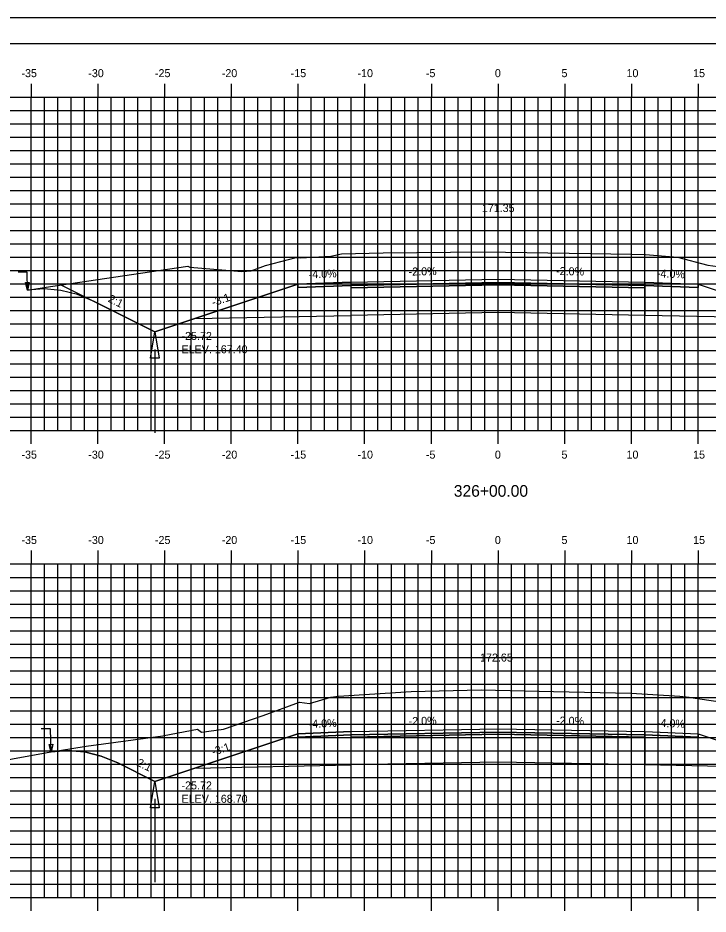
# Model space of a CAD drawing. Extents: x 1140537 to 1140707, y 608981 to 609091.
# Drawn here: x 1140584.3 to 1140636, y 609024.1 to 609091.3 of the extents above; entities that cross this region are included whole.
import ezdxf

# ---------------------------------------------------------------- set-up
doc = ezdxf.new("R2010")
doc.units = 0
for name, color, linetype in [('ANNOTATION', 7, 'Continuous'), ('BORDER', 7, 'Continuous'), ('D_Drainage_Ditch_Line', 7, 'Continuous'), ('D_Roadway_Centerline', 7, 'Continuous'), ('D_Roadway_Centerline_Text', 7, 'Continuous'), ('D_Roadway_Edge_Shoulder', 7, 'Continuous'), ('D_Roadway_Edge_TW', 7, 'Continuous'), ('D_Roadway_Pavement', 7, 'Continuous'), ('D_Roadway_SlopeLines', 7, 'Continuous'), ('D_Roadway_SubGrade', 7, 'Continuous'), ('D_Text_Standard', 7, 'Continuous'), ('H_V ANNOTATION', 7, 'Continuous'), ('MAJOR', 7, 'Continuous'), ('MINOR', 7, 'Continuous'), ('PLOT BOUNDARY', 7, 'Continuous'), ('S_Roadway_Centerline', 7, 'Continuous')]:
    doc.layers.add(name, color=color, linetype=linetype)

msp = doc.modelspace()

# ---------------------------------------------------------------- linework, layer by layer
for points in [[(1140587.473, 609071.258), (1140594.52, 609067.734), (1140597.52, 609068.734), (1140605.244, 609071.309), (1140605.245, 609071.309), (1140609.245, 609071.469), (1140620.245, 609071.689), (1140631.245, 609071.469), (1140635.245, 609071.309), (1140642.968, 609068.735), (1140645.968, 609067.735), (1140660.465, 609074.983), (1140661.715, 609075.533), (1140662.965, 609075.935), (1140664.215, 609076.188), (1140665.465, 609076.292)], [(1140586.756, 609036.254), (1140588.006, 609036.356), (1140589.256, 609036.25), (1140590.506, 609035.937), (1140591.756, 609035.416), (1140594.52, 609034.034), (1140597.52, 609035.034), (1140605.244, 609037.608), (1140605.245, 609037.608), (1140609.245, 609037.768), (1140620.245, 609037.988), (1140631.245, 609037.768), (1140635.245, 609037.608), (1140642.968, 609035.034), (1140645.968, 609034.034), (1140656.415, 609039.257), (1140657.665, 609039.806), (1140658.915, 609040.202), (1140660.165, 609040.445), (1140661.415, 609040.536)]]:
    msp.add_lwpolyline(points)
at = {"layer": 'BORDER'}
msp.add_lwpolyline([(1140545.245, 608984.335), (1140705.245, 608984.335), (1140705.245, 609089.335), (1140545.245, 609089.335)], close=True, dxfattribs=at)
at = {"layer": 'D_Drainage_Ditch_Line'}
for p, q in [((1140594.52, 609066.422), (1140594.52, 609060.179)), ((1140594.52, 609032.721), (1140594.52, 609026.478))]:
    msp.add_line(p, q, dxfattribs=at)
for points in [[(1140594.848, 609065.766), (1140594.192, 609065.766), (1140594.52, 609067.734)], [(1140594.848, 609032.065), (1140594.192, 609032.065), (1140594.52, 609034.034)]]:
    msp.add_lwpolyline(points, close=True, dxfattribs=at)
at = {"layer": 'D_Roadway_Edge_Shoulder'}
for points in [[(1140609.245, 609071.469), (1140605.245, 609071.309), (1140605.245, 609071.059), (1140609.245, 609071.219)], [(1140631.245, 609071.469), (1140635.245, 609071.309), (1140635.245, 609071.059), (1140631.245, 609071.219)], [(1140609.245, 609037.768), (1140605.245, 609037.608), (1140605.245, 609037.358), (1140609.245, 609037.518)], [(1140631.245, 609037.768), (1140635.245, 609037.608), (1140635.245, 609037.358), (1140631.245, 609037.518)]]:
    msp.add_lwpolyline(points, close=True, dxfattribs=at)
at = {"layer": 'D_Roadway_Edge_TW'}
for points in [[(1140609.245, 609071.219), (1140609.245, 609071.469), (1140620.245, 609071.689), (1140631.245, 609071.469), (1140631.245, 609071.219), (1140620.245, 609071.439)], [(1140609.245, 609037.518), (1140609.245, 609037.768), (1140620.245, 609037.988), (1140631.245, 609037.768), (1140631.245, 609037.518), (1140620.245, 609037.738)]]:
    msp.add_lwpolyline(points, close=True, dxfattribs=at)
at = {"layer": 'D_Roadway_Pavement'}
for points in [[(1140609.245, 609071.052), (1140609.245, 609071.219), (1140620.245, 609071.439), (1140631.245, 609071.219), (1140631.245, 609071.052), (1140620.245, 609071.272)], [(1140609.245, 609037.351), (1140609.245, 609037.518), (1140620.245, 609037.738), (1140631.245, 609037.518), (1140631.245, 609037.351), (1140620.245, 609037.571)]]:
    msp.add_lwpolyline(points, close=True, dxfattribs=at)
at = {"layer": 'D_Roadway_SlopeLines'}
for points in [[(1140594.52, 609067.734), (1140589.968, 609070.016), (1140588.718, 609070.537), (1140587.468, 609070.85), (1140586.218, 609070.956), (1140584.968, 609070.854)], [(1140597.52, 609068.734), (1140594.52, 609067.734)], [(1140594.52, 609034.034), (1140591.756, 609035.416), (1140590.506, 609035.937), (1140589.256, 609036.25), (1140588.006, 609036.356), (1140586.756, 609036.254)], [(1140597.52, 609035.034), (1140594.52, 609034.034)]]:
    msp.add_lwpolyline(points, dxfattribs=at)
at = {"layer": 'D_Roadway_SubGrade'}
for points in [[(1140609.245, 609071.052), (1140609.245, 609071.219), (1140605.245, 609071.059), (1140605.245, 609071.309), (1140605.244, 609071.309), (1140597.52, 609068.734), (1140609.245, 609068.969)], [(1140609.245, 609068.969), (1140609.245, 609071.052), (1140620.245, 609071.272), (1140631.245, 609071.052), (1140631.245, 609068.969), (1140620.245, 609069.189)], [(1140631.245, 609071.052), (1140631.245, 609071.219), (1140635.245, 609071.059), (1140635.245, 609071.309), (1140635.245, 609071.309), (1140642.968, 609068.735), (1140631.245, 609068.969)], [(1140609.245, 609037.351), (1140609.245, 609037.518), (1140605.245, 609037.358), (1140605.245, 609037.608), (1140605.244, 609037.608), (1140597.52, 609035.034), (1140609.245, 609035.268)], [(1140609.245, 609035.268), (1140609.245, 609037.351), (1140620.245, 609037.571), (1140631.245, 609037.351), (1140631.245, 609035.268), (1140620.245, 609035.488)], [(1140631.245, 609037.351), (1140631.245, 609037.518), (1140635.245, 609037.358), (1140635.245, 609037.608), (1140635.245, 609037.608), (1140642.968, 609035.034), (1140631.245, 609035.268)]]:
    msp.add_lwpolyline(points, close=True, dxfattribs=at)
at = {"layer": 'D_Text_Standard'}
for points in [[(1140584.968, 609070.854), (1140584.956, 609072.215), (1140584.276, 609072.215)], [(1140586.756, 609036.227), (1140586.691, 609037.975), (1140586.011, 609037.975)]]:
    msp.add_lwpolyline(points, dxfattribs=at)
for points in [[(1140584.968, 609070.854), (1140584.817, 609071.435), (1140585.108, 609071.438)], [(1140586.756, 609036.227), (1140586.589, 609036.804), (1140586.88, 609036.815)]]:
    msp.add_lwpolyline(points, close=True, dxfattribs=at)
at = {"layer": 'MAJOR'}
for p, q in [((1140585.245, 609086.337), (1140585.245, 609085.335)), ((1140590.245, 609086.337), (1140590.245, 609085.335)), ((1140595.245, 609086.337), (1140595.245, 609085.335)), ((1140600.245, 609086.337), (1140600.245, 609085.335)), ((1140605.245, 609086.337), (1140605.245, 609085.335)), ((1140610.245, 609086.337), (1140610.245, 609085.335)), ((1140615.245, 609086.337), (1140615.245, 609085.335)), ((1140620.245, 609086.337), (1140620.245, 609085.335)), ((1140625.245, 609086.337), (1140625.245, 609085.335)), ((1140630.245, 609086.337), (1140630.245, 609085.335)), ((1140635.245, 609086.337), (1140635.245, 609085.335)), ((1140550.245, 609085.335), (1140690.245, 609085.335)), ((1140550.245, 609085.335), (1140690.245, 609085.335)), ((1140585.245, 609060.335), (1140585.245, 609085.335)), ((1140590.245, 609060.335), (1140590.245, 609085.335)), ((1140595.245, 609060.335), (1140595.245, 609085.335)), ((1140600.245, 609060.335), (1140600.245, 609085.335)), ((1140605.245, 609060.335), (1140605.245, 609085.335)), ((1140610.245, 609060.335), (1140610.245, 609085.335)), ((1140615.245, 609060.335), (1140615.245, 609085.335)), ((1140620.245, 609060.335), (1140620.245, 609085.335)), ((1140625.245, 609060.335), (1140625.245, 609085.335)), ((1140630.245, 609060.335), (1140630.245, 609085.335)), ((1140635.245, 609060.335), (1140635.245, 609085.335)), ((1140550.245, 609080.335), (1140690.245, 609080.335)), ((1140550.245, 609075.335), (1140690.245, 609075.335)), ((1140550.245, 609070.335), (1140690.245, 609070.335)), ((1140550.245, 609065.335), (1140690.245, 609065.335)), ((1140550.245, 609060.335), (1140690.245, 609060.335)), ((1140550.245, 609060.335), (1140690.245, 609060.335)), ((1140585.245, 609059.333), (1140585.245, 609060.335)), ((1140590.245, 609059.333), (1140590.245, 609060.335)), ((1140595.245, 609059.333), (1140595.245, 609060.335)), ((1140600.245, 609059.333), (1140600.245, 609060.335)), ((1140605.245, 609059.333), (1140605.245, 609060.335)), ((1140610.245, 609059.333), (1140610.245, 609060.335)), ((1140615.245, 609059.333), (1140615.245, 609060.335)), ((1140620.245, 609059.333), (1140620.245, 609060.335)), ((1140625.245, 609059.333), (1140625.245, 609060.335)), ((1140630.245, 609059.333), (1140630.245, 609060.335)), ((1140635.245, 609059.333), (1140635.245, 609060.335)), ((1140585.245, 609051.337), (1140585.245, 609050.335)), ((1140590.245, 609051.337), (1140590.245, 609050.335)), ((1140595.245, 609051.337), (1140595.245, 609050.335)), ((1140600.245, 609051.337), (1140600.245, 609050.335)), ((1140605.245, 609051.337), (1140605.245, 609050.335)), ((1140610.245, 609051.337), (1140610.245, 609050.335)), ((1140615.245, 609051.337), (1140615.245, 609050.335)), ((1140620.245, 609051.337), (1140620.245, 609050.335)), ((1140625.245, 609051.337), (1140625.245, 609050.335)), ((1140630.245, 609051.337), (1140630.245, 609050.335)), ((1140635.245, 609051.337), (1140635.245, 609050.335)), ((1140550.245, 609050.335), (1140690.245, 609050.335)), ((1140550.245, 609050.335), (1140690.245, 609050.335)), ((1140585.245, 609025.335), (1140585.245, 609050.335)), ((1140590.245, 609025.335), (1140590.245, 609050.335)), ((1140595.245, 609025.335), (1140595.245, 609050.335)), ((1140600.245, 609025.335), (1140600.245, 609050.335)), ((1140605.245, 609025.335), (1140605.245, 609050.335)), ((1140610.245, 609025.335), (1140610.245, 609050.335)), ((1140615.245, 609025.335), (1140615.245, 609050.335)), ((1140620.245, 609025.335), (1140620.245, 609050.335)), ((1140625.245, 609025.335), (1140625.245, 609050.335)), ((1140630.245, 609025.335), (1140630.245, 609050.335)), ((1140635.245, 609025.335), (1140635.245, 609050.335)), ((1140550.245, 609045.335), (1140690.245, 609045.335)), ((1140550.245, 609040.335), (1140690.245, 609040.335)), ((1140550.245, 609035.335), (1140690.245, 609035.335)), ((1140550.245, 609030.335), (1140690.245, 609030.335)), ((1140550.245, 609025.335), (1140690.245, 609025.335)), ((1140550.245, 609025.335), (1140690.245, 609025.335)), ((1140585.245, 609024.333), (1140585.245, 609025.335)), ((1140590.245, 609024.333), (1140590.245, 609025.335)), ((1140595.245, 609024.333), (1140595.245, 609025.335)), ((1140600.245, 609024.333), (1140600.245, 609025.335)), ((1140605.245, 609024.333), (1140605.245, 609025.335)), ((1140610.245, 609024.333), (1140610.245, 609025.335)), ((1140615.245, 609024.333), (1140615.245, 609025.335)), ((1140620.245, 609024.333), (1140620.245, 609025.335)), ((1140625.245, 609024.333), (1140625.245, 609025.335)), ((1140630.245, 609024.333), (1140630.245, 609025.335)), ((1140635.245, 609024.333), (1140635.245, 609025.335))]:
    msp.add_line(p, q, dxfattribs=at)
at = {"layer": 'MINOR'}
for p, q in [((1140586.245, 609060.335), (1140586.245, 609085.335)), ((1140587.245, 609060.335), (1140587.245, 609085.335)), ((1140588.245, 609060.335), (1140588.245, 609085.335)), ((1140589.245, 609060.335), (1140589.245, 609085.335)), ((1140591.245, 609060.335), (1140591.245, 609085.335)), ((1140592.245, 609060.335), (1140592.245, 609085.335)), ((1140593.245, 609060.335), (1140593.245, 609085.335)), ((1140594.245, 609060.335), (1140594.245, 609085.335)), ((1140596.245, 609060.335), (1140596.245, 609085.335)), ((1140597.245, 609060.335), (1140597.245, 609085.335)), ((1140598.245, 609060.335), (1140598.245, 609085.335)), ((1140599.245, 609060.335), (1140599.245, 609085.335)), ((1140601.245, 609060.335), (1140601.245, 609085.335)), ((1140602.245, 609060.335), (1140602.245, 609085.335)), ((1140603.245, 609060.335), (1140603.245, 609085.335)), ((1140604.245, 609060.335), (1140604.245, 609085.335)), ((1140606.245, 609060.335), (1140606.245, 609085.335)), ((1140607.245, 609060.335), (1140607.245, 609085.335)), ((1140608.245, 609060.335), (1140608.245, 609085.335)), ((1140609.245, 609060.335), (1140609.245, 609085.335)), ((1140611.245, 609060.335), (1140611.245, 609085.335)), ((1140612.245, 609060.335), (1140612.245, 609085.335)), ((1140613.245, 609060.335), (1140613.245, 609085.335)), ((1140614.245, 609060.335), (1140614.245, 609085.335)), ((1140616.245, 609060.335), (1140616.245, 609085.335)), ((1140617.245, 609060.335), (1140617.245, 609085.335)), ((1140618.245, 609060.335), (1140618.245, 609085.335)), ((1140619.245, 609060.335), (1140619.245, 609085.335)), ((1140621.245, 609060.335), (1140621.245, 609085.335)), ((1140622.245, 609060.335), (1140622.245, 609085.335)), ((1140623.245, 609060.335), (1140623.245, 609085.335)), ((1140624.245, 609060.335), (1140624.245, 609085.335)), ((1140626.245, 609060.335), (1140626.245, 609085.335)), ((1140627.245, 609060.335), (1140627.245, 609085.335)), ((1140628.245, 609060.335), (1140628.245, 609085.335)), ((1140629.245, 609060.335), (1140629.245, 609085.335)), ((1140631.245, 609060.335), (1140631.245, 609085.335)), ((1140632.245, 609060.335), (1140632.245, 609085.335)), ((1140633.245, 609060.335), (1140633.245, 609085.335)), ((1140634.245, 609060.335), (1140634.245, 609085.335)), ((1140550.245, 609084.335), (1140690.245, 609084.335)), ((1140550.245, 609083.335), (1140690.245, 609083.335)), ((1140550.245, 609082.335), (1140690.245, 609082.335)), ((1140550.245, 609081.335), (1140690.245, 609081.335)), ((1140550.245, 609079.335), (1140690.245, 609079.335)), ((1140550.245, 609078.335), (1140690.245, 609078.335)), ((1140550.245, 609077.335), (1140690.245, 609077.335)), ((1140550.245, 609076.335), (1140690.245, 609076.335)), ((1140550.245, 609074.335), (1140690.245, 609074.335)), ((1140550.245, 609073.335), (1140690.245, 609073.335)), ((1140550.245, 609072.335), (1140690.245, 609072.335)), ((1140550.245, 609071.335), (1140690.245, 609071.335)), ((1140550.245, 609069.335), (1140690.245, 609069.335)), ((1140550.245, 609068.335), (1140690.245, 609068.335)), ((1140550.245, 609067.335), (1140690.245, 609067.335)), ((1140550.245, 609066.335), (1140690.245, 609066.335)), ((1140550.245, 609064.335), (1140690.245, 609064.335)), ((1140550.245, 609063.335), (1140690.245, 609063.335)), ((1140550.245, 609062.335), (1140690.245, 609062.335)), ((1140550.245, 609061.335), (1140690.245, 609061.335)), ((1140586.245, 609025.335), (1140586.245, 609050.335)), ((1140587.245, 609025.335), (1140587.245, 609050.335)), ((1140588.245, 609025.335), (1140588.245, 609050.335)), ((1140589.245, 609025.335), (1140589.245, 609050.335)), ((1140591.245, 609025.335), (1140591.245, 609050.335)), ((1140592.245, 609025.335), (1140592.245, 609050.335)), ((1140593.245, 609025.335), (1140593.245, 609050.335)), ((1140594.245, 609025.335), (1140594.245, 609050.335)), ((1140596.245, 609025.335), (1140596.245, 609050.335)), ((1140597.245, 609025.335), (1140597.245, 609050.335)), ((1140598.245, 609025.335), (1140598.245, 609050.335)), ((1140599.245, 609025.335), (1140599.245, 609050.335)), ((1140601.245, 609025.335), (1140601.245, 609050.335)), ((1140602.245, 609025.335), (1140602.245, 609050.335)), ((1140603.245, 609025.335), (1140603.245, 609050.335)), ((1140604.245, 609025.335), (1140604.245, 609050.335)), ((1140606.245, 609025.335), (1140606.245, 609050.335)), ((1140607.245, 609025.335), (1140607.245, 609050.335)), ((1140608.245, 609025.335), (1140608.245, 609050.335)), ((1140609.245, 609025.335), (1140609.245, 609050.335)), ((1140611.245, 609025.335), (1140611.245, 609050.335)), ((1140612.245, 609025.335), (1140612.245, 609050.335)), ((1140613.245, 609025.335), (1140613.245, 609050.335)), ((1140614.245, 609025.335), (1140614.245, 609050.335)), ((1140616.245, 609025.335), (1140616.245, 609050.335)), ((1140617.245, 609025.335), (1140617.245, 609050.335)), ((1140618.245, 609025.335), (1140618.245, 609050.335)), ((1140619.245, 609025.335), (1140619.245, 609050.335)), ((1140621.245, 609025.335), (1140621.245, 609050.335)), ((1140622.245, 609025.335), (1140622.245, 609050.335)), ((1140623.245, 609025.335), (1140623.245, 609050.335)), ((1140624.245, 609025.335), (1140624.245, 609050.335)), ((1140626.245, 609025.335), (1140626.245, 609050.335)), ((1140627.245, 609025.335), (1140627.245, 609050.335)), ((1140628.245, 609025.335), (1140628.245, 609050.335)), ((1140629.245, 609025.335), (1140629.245, 609050.335)), ((1140631.245, 609025.335), (1140631.245, 609050.335)), ((1140632.245, 609025.335), (1140632.245, 609050.335)), ((1140633.245, 609025.335), (1140633.245, 609050.335)), ((1140634.245, 609025.335), (1140634.245, 609050.335)), ((1140550.245, 609049.335), (1140690.245, 609049.335)), ((1140550.245, 609048.335), (1140690.245, 609048.335)), ((1140550.245, 609047.335), (1140690.245, 609047.335)), ((1140550.245, 609046.335), (1140690.245, 609046.335)), ((1140550.245, 609044.335), (1140690.245, 609044.335)), ((1140550.245, 609043.335), (1140690.245, 609043.335)), ((1140550.245, 609042.335), (1140690.245, 609042.335)), ((1140550.245, 609041.335), (1140690.245, 609041.335)), ((1140550.245, 609039.335), (1140690.245, 609039.335)), ((1140550.245, 609038.335), (1140690.245, 609038.335)), ((1140550.245, 609037.335), (1140690.245, 609037.335)), ((1140550.245, 609036.335), (1140690.245, 609036.335)), ((1140550.245, 609034.335), (1140690.245, 609034.335)), ((1140550.245, 609033.335), (1140690.245, 609033.335)), ((1140550.245, 609032.335), (1140690.245, 609032.335)), ((1140550.245, 609031.335), (1140690.245, 609031.335)), ((1140550.245, 609029.335), (1140690.245, 609029.335)), ((1140550.245, 609028.335), (1140690.245, 609028.335)), ((1140550.245, 609027.335), (1140690.245, 609027.335)), ((1140550.245, 609026.335), (1140690.245, 609026.335))]:
    msp.add_line(p, q, dxfattribs=at)
at = {"layer": 'PLOT BOUNDARY'}
msp.add_lwpolyline([(1140537.151, 608981.276), (1140707.151, 608981.276), (1140707.151, 609091.276), (1140537.151, 609091.276)], close=True, dxfattribs=at)
at = {"layer": 'S_Roadway_Centerline'}
for points in [[(1140584.968, 609070.854), (1140586.71, 609071.145), (1140597, 609072.667), (1140597.149, 609072.6), (1140601.038, 609072.265), (1140601.748, 609072.31), (1140602.82, 609072.72), (1140605.119, 609073.302), (1140605.433, 609073.301), (1140607.715, 609073.426), (1140608.508, 609073.585), (1140611.63, 609073.668), (1140619.191, 609073.741), (1140627.177, 609073.626), (1140630.213, 609073.553), (1140631.292, 609073.547), (1140633.688, 609073.335), (1140635.963, 609072.743), (1140636.719, 609072.645)], [(1140568.516, 609032.928), (1140586.442, 609036.203), (1140589.364, 609036.683), (1140595.12, 609037.457), (1140595.232, 609037.472), (1140597.724, 609037.95), (1140598.011, 609037.721), (1140599.664, 609037.945), (1140602.639, 609038.97), (1140605.355, 609039.978), (1140606.119, 609039.883), (1140607.708, 609040.341), (1140608.295, 609040.438), (1140613.728, 609040.772), (1140618.974, 609040.9), (1140624.409, 609040.769), (1140630.227, 609040.641), (1140633.873, 609040.427), (1140634.56, 609040.361), (1140635.028, 609040.273), (1140638.111, 609039.824)]]:
    msp.add_lwpolyline(points, dxfattribs=at)

# ---------------------------------------------------------------- texts
at = {"layer": 'ANNOTATION'}
for s, rotation, p in [('-2.0%', 1.14576, (1140613.548, 609071.955)), ('-2.0%', 358.85424, (1140624.588, 609072.002)), ('-4.0%', 2.29061, (1140606.06, 609071.742)), ('-4.0%', 357.70939, (1140632.14, 609071.834)), ('2:1', 333.43495, (1140590.963, 609070.031)), ('-3:1', 18.43482, (1140598.899, 609069.648)), ('-2.0%', 1.14576, (1140613.548, 609038.254)), ('-2.0%', 358.85424, (1140624.588, 609038.301)), ('-4.0%', 2.29061, (1140606.06, 609038.042)), ('-4.0%', 357.70939, (1140632.14, 609038.133)), ('-3:1', 18.43482, (1140598.899, 609035.947)), ('2:1', 333.43495, (1140593.105, 609035.259))]:
    msp.add_text(s, height=0.6, rotation=rotation, dxfattribs=at).set_placement(p)
at = {"layer": 'D_Roadway_Centerline'}
for s, p in [('C', (1140620.239, 609071.689)), ('L', (1140620.245, 609071.682)), ('C', (1140620.239, 609037.988)), ('L', (1140620.245, 609037.981))]:
    msp.add_text(s, height=0.0146, dxfattribs=at).set_placement(p)
at = {"layer": 'D_Roadway_Centerline_Text'}
for s, p in [('171.35', (1140619.027, 609076.721)), ('172.65', (1140618.893, 609043.02))]:
    msp.add_text(s, height=0.6, dxfattribs=at).set_placement(p)
at = {"layer": 'D_Text_Standard'}
for s, p in [('-25.72', (1140596.52, 609067.134)), ('ELEV. 167.40', (1140596.52, 609066.132)), ('-25.72', (1140596.52, 609033.434)), ('ELEV. 168.70', (1140596.52, 609032.432))]:
    msp.add_text(s, height=0.6, dxfattribs=at).set_placement(p)
at = {"layer": 'H_V ANNOTATION'}
for s, height, p in [('-35', 0.6, (1140584.525, 609086.835)), ('-30', 0.6, (1140589.533, 609086.835)), ('-25', 0.6, (1140594.53, 609086.835)), ('-20', 0.6, (1140599.538, 609086.835)), ('-15', 0.6, (1140604.701, 609086.835)), ('-10', 0.6, (1140609.709, 609086.835)), ('-5', 0.6, (1140614.835, 609086.835)), ('0', 0.6, (1140620.004, 609086.835)), ('5', 0.6, (1140624.996, 609086.835)), ('10', 0.6, (1140629.87, 609086.835)), ('15', 0.6, (1140634.862, 609086.835)), ('-35', 0.6, (1140584.525, 609058.235)), ('-30', 0.6, (1140589.533, 609058.235)), ('-25', 0.6, (1140594.53, 609058.235)), ('-20', 0.6, (1140599.538, 609058.235)), ('-15', 0.6, (1140604.701, 609058.235)), ('-10', 0.6, (1140609.709, 609058.235)), ('-5', 0.6, (1140614.835, 609058.235)), ('0', 0.6, (1140620.004, 609058.235)), ('5', 0.6, (1140624.996, 609058.235)), ('10', 0.6, (1140629.87, 609058.235)), ('15', 0.6, (1140634.862, 609058.235)), ('326+00.00', 0.875, (1140616.928, 609055.378)), ('-35', 0.6, (1140584.525, 609051.835)), ('-30', 0.6, (1140589.533, 609051.835)), ('-25', 0.6, (1140594.53, 609051.835)), ('-20', 0.6, (1140599.538, 609051.835)), ('-15', 0.6, (1140604.701, 609051.835)), ('-10', 0.6, (1140609.709, 609051.835)), ('-5', 0.6, (1140614.835, 609051.835)), ('0', 0.6, (1140620.004, 609051.835)), ('5', 0.6, (1140624.996, 609051.835)), ('10', 0.6, (1140629.87, 609051.835)), ('15', 0.6, (1140634.862, 609051.835))]:
    msp.add_text(s, height=height, dxfattribs=at).set_placement(p)
at = {"layer": 'S_Roadway_Centerline'}
for s, p in [('L', (1140619.182, 609073.733)), ('C', (1140619.185, 609073.741)), ('L', (1140618.966, 609040.893)), ('C', (1140618.969, 609040.9))]:
    msp.add_text(s, height=0.0146, dxfattribs=at).set_placement(p)

doc.saveas('drawing.dxf')
